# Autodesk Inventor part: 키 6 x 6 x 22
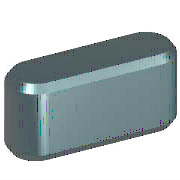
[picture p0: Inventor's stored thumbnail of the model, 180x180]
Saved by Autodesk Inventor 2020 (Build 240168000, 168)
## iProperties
Created: 2012-02
Part Number: 키 6 x 6 x 22
Material: 강철, 연강
Description: 키 및 해당 키홈
Document SubType Name: Modeling
Standard: KS B 1311
Designer: mduedu
Standards Organization: KS
Language: ko-KR
Size Designation: 6 x 6 x 22
Categories: <MemberInstance><Categories><Category DisplayName="샤프트 부품" InternalName="7f7aeb1f-a693-4053-b835-cee3144e0d98" Mnemonic="SHFT"><Category DisplayName="키" Interna
Density: 7.86 g/cm^3
Mass: 5.79788 g
Surface Area: 5.294 cm^2
Volume: 0.737644 cm^3
Appearance: 노란색
IsCustomPart: 1
Author: mduedu
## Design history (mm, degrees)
workplane "Work Plane1"
workplane "Work Plane2"
sketch "스케치1"
  geometry: L1 (3, 3)-(19, 3); L2 (19, -3)-(3, -3); L3 (0, 9.4)-(0, -7.4) reference; L4 (-5, 0)-(30, 0) reference; L5 (22, 0)-(22, 7); A1 r 3 centre (3, 0) between (3, 3) and (3, -3); A2 r 3 centre (19, 0) between (19, -3) and (19, 3)
  constraints: 6 end point, 5 point on circle, 4 tangent, 3 point on line, 2 centre point, 1 horizontal, 1 parallel, 1 perpendicular
  dimensions: "d0" = 3 radius of A1 (= 0.5 x PB); "d13" = 3 radius of A2 (= 0.5 x PB); "d14" = 22 distance between parallel lines of L5 L3 (= NLG)
extrude "본체1" new body sketch "스케치1" taper "d3" = 0 deg; stored distance "d4" = 10
workplane "Work Plane3"
body "Solid1"
chamfer "모따기1" distance "d8" = 0.4 (= PHH); stored, may be unused: second distance "d9" = 0.4 (= PHH), angle "d15" = 45 deg
other parameters: "d1" = -3.5 (= -PNT), "d2" = 2.5 (= PH - PNT), "NLG" = 22 [user parameter; used in 3 equation terms], "PB" = 6 [user parameter; used in 2 equation terms], "PNT" = 3.5 [user parameter; used in 2 equation terms], "PH" = 6 [user parameter; used in 1 equation term], "PHH" = 0.4 [user parameter; used in 2 equation terms], "d10" = 0, "d16" = 0, "d17" = 0, "d18" = 0, "WDMIN" = 17 [user parameter], "PLB2" = 22 (= NLG) [user parameter], "WDMAX" = 22 [user parameter], "PLB1" = 22 (= NLG) [user parameter], "RR" = 0.16 [user parameter], "PUEB" = 2.8 [user parameter]
